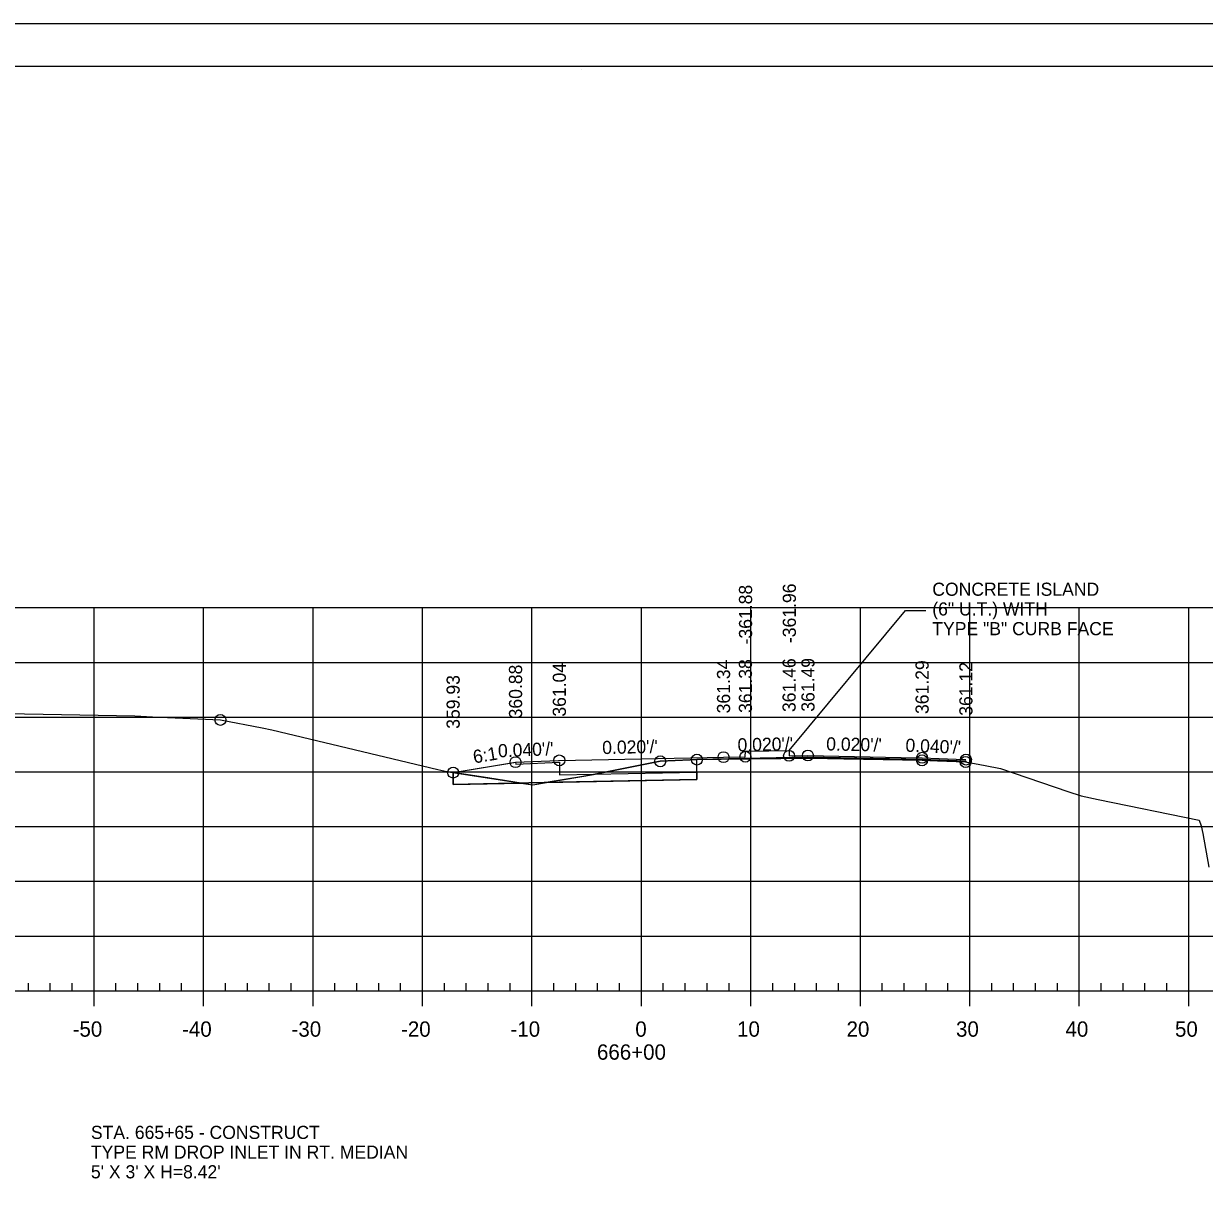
# Model space of a CAD drawing. Extents: x 1359801 to 1362404, y 372415 to 374228.
# Drawn here: x 1359914.9 to 1360022.8, y 373482.2 to 373588 of the extents above; entities that cross this region are included whole.
import ezdxf

# ---------------------------------------------------------------- set-up
doc = ezdxf.new("R2010")
doc.units = 0
for name, color, linetype in [('S_CROSS_DRAIN_ANNOT', 7, 'Continuous'), ('S_DRG_PT_SYM', 7, 'Continuous'), ('S_DRIVEWAY', 7, 'Continuous'), ('S_ELECTRIC_UTILITIES_ANNOT', 7, 'Continuous'), ('S_IRON_PIN', 7, 'Continuous'), ('S_MAILBOX', 7, 'Continuous'), ('S_PRIMARY_CTL', 7, 'Continuous'), ('S_SANITARY_SEWER', 7, 'Continuous'), ('S_SHOULDER', 7, 'Continuous'), ('S_TELEPHONE_UTILITIES_ANNOT', 7, 'Continuous'), ('S_UNDERGROUND_CABLE', 7, 'Continuous'), ('S_UTILITY_POLE_ANNOT', 7, 'Continuous'), ('S_UTL_PT_SYM', 7, 'Continuous'), ('S_WATER_UTILITIES', 7, 'Continuous')]:
    doc.layers.add(name, color=color, linetype=linetype)

msp = doc.modelspace()

# ---------------------------------------------------------------- linework, layer by layer
at = {"layer": 'S_DRG_PT_SYM'}
msp.add_lwpolyline([(1359906.58, 373525.04), (1359925.06, 373524.7), (1359926.69, 373524.63), (1359932.89, 373524.34), (1359936.71, 373523.63), (1359937.6, 373523.44), (1359952.75, 373519.81), (1359953.57, 373519.62), (1359953.71, 373519.6), (1359961.42, 373518.41), (1359966.97, 373519.35), (1359973.07, 373520.56), (1359975.79, 373520.69), (1359976.42, 373520.72), (1359978.64, 373520.75), (1359986.84, 373520.84), (1359989.83, 373520.78), (1359996.99, 373520.65), (1359998.4, 373520.6), (1360000.96, 373520.5), (1360002.74, 373520.18), (1360004.14, 373519.91), (1360010.3, 373517.79), (1360011.52, 373517.4), (1360013.08, 373517.07), (1360022.29, 373515.17), (1360022.48, 373514.66), (1360022.64, 373513.97), (1360023.19, 373510.89)], dxfattribs=at)
at = {"layer": 'S_ELECTRIC_UTILITIES_ANNOT'}
for p, q in [((1359976.42, 373519.39), (1359976.42, 373520.72)), ((1360000.99, 373520.56), (1359996.99, 373520.72)), ((1360000.99, 373520.56), (1360001.03, 373520.46)), ((1360001.02, 373520.49), (1360000.99, 373520.56)), ((1359954.15, 373519.53), (1359954.16, 373518.94)), ((1359954.16, 373519.53), (1359954.15, 373519.53)), ((1359957.51, 373519.01), (1359954.16, 373519.53)), ((1359962.66, 373518.61), (1359960.37, 373518.57)), ((1359962.66, 373518.61), (1359962.66, 373518.61))]:
    msp.add_line(p, q, dxfattribs=at)
for points in [[(1359976.42, 373520.72), (1359975.79, 373520.69), (1359973.07, 373520.56), (1359966.97, 373519.35), (1359966.01, 373519.18)], [(1359996.99, 373520.72), (1359986.56, 373520.93), (1359976.42, 373520.72)], [(1359976.42, 373520.72), (1359978.64, 373520.75), (1359986.84, 373520.84), (1359989.83, 373520.78), (1359996.99, 373520.65), (1359998.4, 373520.6), (1360000.96, 373520.5), (1360001.02, 373520.49)], [(1359966.01, 373519.18), (1359962.66, 373518.61), (1359976.42, 373518.89), (1359976.42, 373519.39)], [(1359954.16, 373518.94), (1359954.16, 373518.44), (1359960.37, 373518.57), (1359957.51, 373519.01)], [(1359960.37, 373518.57), (1359961.42, 373518.41), (1359962.66, 373518.61)]]:
    msp.add_lwpolyline(points, dxfattribs=at)
at = {"layer": 'S_MAILBOX'}
for p, q in [((1359826.35, 373534.6), (1360116.35, 373534.6)), ((1359826.35, 373534.6), (1360116.35, 373534.6)), ((1359921.35, 373499.6), (1359921.35, 373534.6)), ((1359921.35, 373499.6), (1359921.35, 373534.6)), ((1359931.35, 373499.6), (1359931.35, 373534.6)), ((1359931.35, 373499.6), (1359931.35, 373534.6)), ((1359941.35, 373499.6), (1359941.35, 373534.6)), ((1359941.35, 373499.6), (1359941.35, 373534.6)), ((1359951.35, 373499.6), (1359951.35, 373534.6)), ((1359951.35, 373499.6), (1359951.35, 373534.6)), ((1359961.35, 373499.6), (1359961.35, 373534.6)), ((1359961.35, 373499.6), (1359961.35, 373534.6)), ((1359971.35, 373499.6), (1359971.35, 373534.6)), ((1359971.35, 373499.6), (1359971.35, 373534.6)), ((1359981.35, 373499.6), (1359981.35, 373534.6)), ((1359981.35, 373499.6), (1359981.35, 373534.6)), ((1359991.35, 373499.6), (1359991.35, 373534.6)), ((1359991.35, 373499.6), (1359991.35, 373534.6)), ((1360001.35, 373499.6), (1360001.35, 373534.6)), ((1360001.35, 373499.6), (1360001.35, 373534.6)), ((1360011.35, 373499.6), (1360011.35, 373534.6)), ((1360011.35, 373499.6), (1360011.35, 373534.6)), ((1360021.35, 373499.6), (1360021.35, 373534.6)), ((1360021.35, 373499.6), (1360021.35, 373534.6)), ((1359826.35, 373529.6), (1360116.35, 373529.6)), ((1359826.35, 373529.6), (1360116.35, 373529.6)), ((1359826.35, 373524.6), (1360116.35, 373524.6)), ((1359826.35, 373524.6), (1360116.35, 373524.6)), ((1359826.35, 373519.6), (1360116.35, 373519.6)), ((1359826.35, 373519.6), (1360116.35, 373519.6)), ((1359826.35, 373514.6), (1360116.35, 373514.6)), ((1359826.35, 373514.6), (1360116.35, 373514.6)), ((1359826.35, 373509.6), (1360116.35, 373509.6)), ((1359826.35, 373509.6), (1360116.35, 373509.6)), ((1359826.35, 373504.6), (1360116.35, 373504.6)), ((1359826.35, 373504.6), (1360116.35, 373504.6)), ((1359826.35, 373499.6), (1360116.35, 373499.6)), ((1359826.35, 373499.6), (1360116.35, 373499.6))]:
    msp.add_line(p, q, dxfattribs=at)
at = {"layer": 'S_SANITARY_SEWER'}
msp.add_lwpolyline([(1359954.15, 373519.53), (1359959.7, 373520.45), (1359959.85, 373520.48), (1359963.78, 373520.64), (1359963.85, 373520.64), (1359971.32, 373520.79), (1359978.85, 373520.94), (1359980.84, 373520.98), (1359980.85, 373521.48), (1359981.15, 373521.48), (1359984.84, 373521.56), (1359984.84, 373521.06), (1359986.56, 373521.09), (1359995.09, 373520.92), (1359996.99, 373520.88), (1360000.11, 373520.76), (1360000.99, 373520.72)], dxfattribs=at)
at = {"layer": 'S_SHOULDER'}
for p, q in [((1359800.95, 373587.95), (1360134.28, 373587.95)), ((1359959.87, 373520.31), (1359963.86, 373520.47)), ((1359954.16, 373518.44), (1359954.16, 373519.53)), ((1359963.88, 373519.31), (1359976.42, 373519.56))]:
    msp.add_line(p, q, dxfattribs=at)
for points in [[(1359800.94, 373587.95), (1360134.28, 373587.95), (1360134.28, 373374.61), (1359800.94, 373374.61)], [(1360047.27, 373584.06), (1360047.27, 373574.18), (1360083, 373574.18), (1360083, 373571.26), (1360106.2, 373571.26), (1360106.2, 373546.93), (1360129.53, 373546.93), (1360129.53, 373378.6), (1359813.35, 373378.6), (1359813.35, 373584.06)]]:
    msp.add_lwpolyline(points, close=True, dxfattribs=at)
for points in [[(1359954.16, 373519.53), (1359959.85, 373520.48), (1359959.87, 373520.31)], [(1359963.86, 373520.47), (1359963.88, 373519.31)], [(1359976.42, 373519.56), (1359976.42, 373518.89), (1359963.85, 373518.64), (1359954.16, 373518.44)]]:
    msp.add_lwpolyline(points, dxfattribs=at)
for centre in [(1359932.89, 373524.34), (1359984.84, 373521.06), (1359986.56, 373521.09), (1359959.85, 373520.48), (1359963.85, 373520.64), (1359973.07, 373520.56), (1359976.42, 373520.72), (1359978.85, 373520.94), (1359980.85, 373520.98), (1359996.99, 373520.88), (1359996.99, 373520.65), (1360000.96, 373520.5), (1360000.99, 373520.72), (1359954.15, 373519.53)]:
    msp.add_circle(centre, 0.5, dxfattribs=at)
at = {"layer": 'S_TELEPHONE_UTILITIES_ANNOT'}
msp.add_lwpolyline([(1359984.84, 373521.56), (1359995.46, 373534.34), (1359995.46, 373534.34), (1359997.32, 373534.34)], dxfattribs=at)
at = {"layer": 'S_UNDERGROUND_CABLE'}
msp.add_line((1359954.16, 373519.53), (1359954.16, 373518.44), dxfattribs=at)
msp.add_lwpolyline([(1359954.16, 373518.44), (1359963.85, 373518.64), (1359976.42, 373518.89), (1359976.42, 373520.72), (1359986.56, 373520.93), (1359996.99, 373520.72), (1360000.99, 373520.56)], dxfattribs=at)
at = {"layer": 'S_UTL_PT_SYM'}
for p, q in [((1359813.35, 373584.06), (1360129.53, 373584.06)), ((1359965.87, 373583.8), (1359965.87, 373583.8)), ((1359965.87, 373583.8), (1359965.87, 373583.8))]:
    msp.add_line(p, q, dxfattribs=at)
at = {"layer": 'S_WATER_UTILITIES'}
for p, q in [((1359915.35, 373499.6), (1359915.35, 373500.3)), ((1359917.35, 373499.6), (1359917.35, 373500.3)), ((1359919.35, 373499.6), (1359919.35, 373500.3)), ((1359923.35, 373499.6), (1359923.35, 373500.3)), ((1359925.35, 373499.6), (1359925.35, 373500.3)), ((1359927.35, 373499.6), (1359927.35, 373500.3)), ((1359929.35, 373499.6), (1359929.35, 373500.3)), ((1359933.35, 373499.6), (1359933.35, 373500.3)), ((1359935.35, 373499.6), (1359935.35, 373500.3)), ((1359937.35, 373499.6), (1359937.35, 373500.3)), ((1359939.35, 373499.6), (1359939.35, 373500.3)), ((1359943.35, 373499.6), (1359943.35, 373500.3)), ((1359945.35, 373499.6), (1359945.35, 373500.3)), ((1359947.35, 373499.6), (1359947.35, 373500.3)), ((1359949.35, 373499.6), (1359949.35, 373500.3)), ((1359953.35, 373499.6), (1359953.35, 373500.3)), ((1359955.35, 373499.6), (1359955.35, 373500.3)), ((1359957.35, 373499.6), (1359957.35, 373500.3)), ((1359959.35, 373499.6), (1359959.35, 373500.3)), ((1359963.35, 373499.6), (1359963.35, 373500.3)), ((1359965.35, 373499.6), (1359965.35, 373500.3)), ((1359967.35, 373499.6), (1359967.35, 373500.3)), ((1359969.35, 373499.6), (1359969.35, 373500.3)), ((1359973.35, 373499.6), (1359973.35, 373500.3)), ((1359975.35, 373499.6), (1359975.35, 373500.3)), ((1359977.35, 373499.6), (1359977.35, 373500.3)), ((1359979.35, 373499.6), (1359979.35, 373500.3)), ((1359983.35, 373499.6), (1359983.35, 373500.3)), ((1359985.35, 373499.6), (1359985.35, 373500.3)), ((1359987.35, 373499.6), (1359987.35, 373500.3)), ((1359989.35, 373499.6), (1359989.35, 373500.3)), ((1359993.35, 373499.6), (1359993.35, 373500.3)), ((1359995.35, 373499.6), (1359995.35, 373500.3)), ((1359997.35, 373499.6), (1359997.35, 373500.3)), ((1359999.35, 373499.6), (1359999.35, 373500.3)), ((1360003.35, 373499.6), (1360003.35, 373500.3)), ((1360005.35, 373499.6), (1360005.35, 373500.3)), ((1360007.35, 373499.6), (1360007.35, 373500.3)), ((1360009.35, 373499.6), (1360009.35, 373500.3)), ((1360013.35, 373499.6), (1360013.35, 373500.3)), ((1360015.35, 373499.6), (1360015.35, 373500.3)), ((1360017.35, 373499.6), (1360017.35, 373500.3)), ((1360019.35, 373499.6), (1360019.35, 373500.3)), ((1359826.35, 373499.6), (1360116.35, 373499.6)), ((1359921.35, 373498.2), (1359921.35, 373499.6)), ((1359931.35, 373498.2), (1359931.35, 373499.6)), ((1359941.35, 373498.2), (1359941.35, 373499.6)), ((1359951.35, 373498.2), (1359951.35, 373499.6)), ((1359961.35, 373498.2), (1359961.35, 373499.6)), ((1359971.35, 373498.2), (1359971.35, 373499.6)), ((1359981.35, 373498.2), (1359981.35, 373499.6)), ((1359991.35, 373498.2), (1359991.35, 373499.6)), ((1360001.35, 373498.2), (1360001.35, 373499.6)), ((1360011.35, 373498.2), (1360011.35, 373499.6)), ((1360021.35, 373498.2), (1360021.35, 373499.6))]:
    msp.add_line(p, q, dxfattribs=at)

# ---------------------------------------------------------------- texts
at = {"layer": 'S_CROSS_DRAIN_ANNOT'}
for s, p in [('-361.88', (1359981.46, 373531.24)), ('-361.96', (1359985.46, 373531.36))]:
    msp.add_text(s, height=1.2, rotation=90, dxfattribs=at).set_placement(p)
at = {"layer": 'S_DRIVEWAY'}
for s, p in [('CONCRETE ISLAND', (1359997.92, 373535.68)), ('(6" U.T.) WITH', (1359997.92, 373533.88)), ('TYPE "B" CURB FACE', (1359997.92, 373532.08))]:
    msp.add_text(s, height=1.2, dxfattribs=at).set_placement(p)
at = {"layer": 'S_IRON_PIN'}
for s, rotation, p in [('360.88', 90, (1359960.45, 373524.48)), ('361.04', 90, (1359964.45, 373524.64)), ('361.34', 90, (1359979.45, 373524.94)), ('361.38', 90, (1359981.45, 373524.98)), ('361.46', 90, (1359985.44, 373525.06)), ('361.49', 90, (1359987.16, 373525.09)), ('361.29', 90, (1359997.59, 373524.88)), ('361.12', 90, (1360001.59, 373524.72)), ('359.93', 90, (1359954.75, 373523.53)), ("0.020'/'", 1.1446, (1359967.78, 373521.22)), ("0.020'/'", 1.1404, (1359980.14, 373521.46)), ("0.020'/'", 358.8515, (1359988.22, 373521.56)), ("0.040'/'", 357.7069, (1359995.45, 373521.44)), ('6:1', 9.4631, (1359956.07, 373520.36)), ("0.040'/'", 2.2899, (1359958.27, 373520.92))]:
    msp.add_text(s, height=1.2, rotation=rotation, dxfattribs=at).set_placement(p)
at = {"layer": 'S_PRIMARY_CTL'}
for s, p in [('-50', (1359919.39, 373495.4)), ('-40', (1359929.39, 373495.4)), ('-30', (1359939.39, 373495.4)), ('-20', (1359949.39, 373495.4)), ('-10', (1359959.39, 373495.4)), ('0', (1359970.79, 373495.4)), ('10', (1359980.09, 373495.4)), ('20', (1359990.09, 373495.4)), ('30', (1360000.09, 373495.4)), ('40', (1360010.09, 373495.4)), ('50', (1360020.09, 373495.4)), ('666+00', (1359967.29, 373493.3))]:
    msp.add_text(s, height=1.4, dxfattribs=at).set_placement(p)
at = {"layer": 'S_SHOULDER'}
msp.add_text('+', height=0.1, dxfattribs=at).set_placement((1359925.01, 373524.65))
at = {"layer": 'S_UTILITY_POLE_ANNOT'}
for s, p in [('STA. 665+65 - CONSTRUCT', (1359921.06, 373486.06)), ('TYPE RM DROP INLET IN RT. MEDIAN', (1359921.06, 373484.26)), ("5' X 3' X H=8.42'", (1359921.06, 373482.46))]:
    msp.add_text(s, height=1.2, dxfattribs=at).set_placement(p)

doc.saveas('drawing.dxf')
